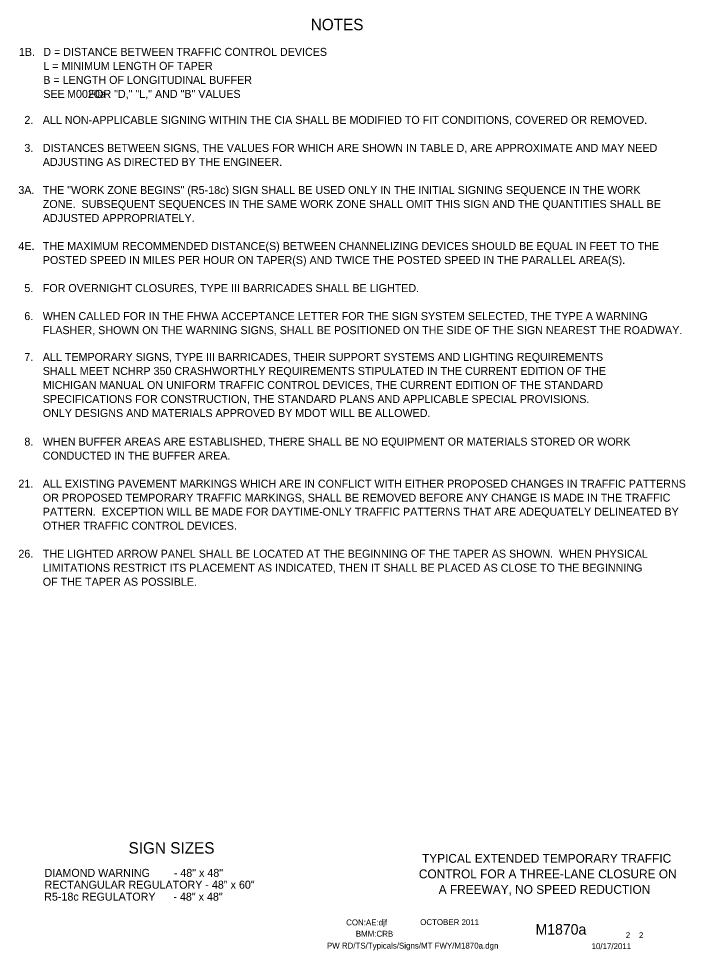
# Model space of a CAD drawing. Extents: x 16724 to 18475, y 7025 to 8210.
# Drawn here: x 17776 to 18475, y 7218 to 8195 of the extents above; entities that cross this region are included whole.
import ezdxf

# ---------------------------------------------------------------- set-up
doc = ezdxf.new("R2010")
doc.units = 0
for name, color, linetype in [('BORDER', 7, 'Continuous'), ('BORDER_SIGNAL_WO', 7, 'Continuous'), ('TYPICAL_TEXT_DIMEN_PR', 7, 'Continuous')]:
    doc.layers.add(name, color=color, linetype=linetype)

msp = doc.modelspace()

# ---------------------------------------------------------------- linework, layer by layer
at = {"layer": 'BORDER'}
msp.add_line((18318.25, 7297.5), (18318.25, 7297.5), dxfattribs=at)

# ---------------------------------------------------------------- texts
for s, p in [('TYPICAL EXTENDED TEMPORARY TRAFFIC', (18199.19, 7309.95)), ('CONTROL FOR A THREE-LANE CLOSURE ON', (18195.91, 7293.65)), ('A FREEWAY, NO SPEED REDUCTION', (18216.69, 7277.35))]:
    msp.add_text(s, height=9.3, dxfattribs=at).set_placement(p)
at = {"layer": 'BORDER_SIGNAL_WO'}
for s, height, p in [('CON:AE:djf  ', 6.2, (18119.69, 7244.31)), ('    OCTOBER 2011', 6.2, (18188.08, 7244.59)), ('    M1870a   ', 11, (18301.86, 7234.63)), ('BMM:CRB', 6.2, (18129.81, 7232.42)), (' 2    2 ', 6.2, (18410.45, 7230.95)), ('PW RD/TS/Typicals/Signs/MT FWY/M1870a.dgn      ', 6.2, (18099.55, 7219.96)), ('10/17/2011', 6.2, (18376.93, 7219.38))]:
    msp.add_text(s, height=height, dxfattribs=at).set_placement(p)
at = {"layer": 'TYPICAL_TEXT_DIMEN_PR'}
for s, height, p in [('NOTES', 12, (18082.55, 8183.25)), ('1B.', 8.4, (17776.71, 8156.36)), ('D = DISTANCE BETWEEN TRAFFIC CONTROL DEVICES', 8.4, (17802.22, 8156.36)), ('L = MINIMUM LENGTH OF TAPER', 8.4, (17802.22, 8141.66)), ('B = LENGTH OF LONGITUDINAL BUFFER', 8.4, (17802.22, 8126.96)), ('SEE        FOR "D," "L," AND "B" VALUES', 8.4, (17802.22, 8112.26)), ('M0020a', 8.4, (17827.14, 8112.26)), ('2.', 8.4, (17782.39, 8085)), ('ALL NON-APPLICABLE SIGNING WITHIN THE CIA SHALL BE MODIFIED TO FIT CONDITIONS, COVERED OR REMOVED.', 8.4, (17801.7, 8085)), ('3.', 8.4, (17782.39, 8055.6)), ('DISTANCES BETWEEN SIGNS, THE VALUES FOR WHICH ARE SHOWN IN TABLE D, ARE APPROXIMATE AND MAY NEED', 8.4, (17801.7, 8055.6)), ('ADJUSTING AS DIRECTED BY THE ENGINEER.', 8.4, (17801.7, 8040.9)), ('3A.', 8.4, (17776.09, 8011.49)), ('THE "WORK ZONE BEGINS" (R5-18c) SIGN SHALL BE USED ONLY IN THE INITIAL SIGNING SEQUENCE IN THE WORK', 8.4, (17801.7, 8011.49)), ('ZONE.  SUBSEQUENT SEQUENCES IN THE SAME WORK ZONE SHALL OMIT THIS SIGN AND THE QUANTITIES SHALL BE', 8.4, (17801.7, 7996.79)), ('ADJUSTED APPROPRIATELY.', 8.4, (17801.7, 7982.09)), ('4E.', 8.4, (17776.13, 7952.7)), ('THE MAXIMUM RECOMMENDED DISTANCE(S) BETWEEN CHANNELIZING DEVICES SHOULD BE EQUAL IN FEET TO THE', 8.4, (17801.7, 7952.7)), ('POSTED SPEED IN MILES PER HOUR ON TAPER(S) AND TWICE THE POSTED SPEED IN THE PARALLEL AREA(S).', 8.4, (17801.7, 7938)), ('5.', 8.4, (17782.39, 7908.6)), ('FOR OVERNIGHT CLOSURES, TYPE III BARRICADES SHALL BE LIGHTED.', 8.4, (17801.7, 7908.6)), ('6.', 8.4, (17782.34, 7879.2)), ('WHEN CALLED FOR IN THE FHWA ACCEPTANCE LETTER FOR THE SIGN SYSTEM SELECTED, THE TYPE A WARNING ', 8.4, (17801.7, 7879.2)), ('FLASHER, SHOWN ON THE WARNING SIGNS, SHALL BE POSITIONED ON THE SIDE OF THE SIGN NEAREST THE ROADWAY.', 8.4, (17801.7, 7864.5)), ('7.', 8.4, (17782.34, 7836.33)), ('ALL TEMPORARY SIGNS, TYPE III BARRICADES, THEIR SUPPORT SYSTEMS AND LIGHTING REQUIREMENTS', 8.4, (17801.7, 7836.35)), ('SHALL MEET NCHRP 350 CRASHWORTHLY REQUIREMENTS STIPULATED IN THE CURRENT EDITION OF THE', 8.4, (17801.7, 7821.65)), ('MICHIGAN MANUAL ON UNIFORM TRAFFIC CONTROL DEVICES, THE CURRENT EDITION OF THE STANDARD', 8.4, (17801.7, 7806.95)), ('SPECIFICATIONS FOR CONSTRUCTION, THE STANDARD PLANS AND APPLICABLE SPECIAL PROVISIONS.', 8.4, (17801.7, 7792.25)), ('ONLY DESIGNS AND MATERIALS APPROVED BY MDOT WILL BE ALLOWED.', 8.4, (17801.7, 7777.55)), ('8.', 8.4, (17782.39, 7747.54)), ('WHEN BUFFER AREAS ARE ESTABLISHED, THERE SHALL BE NO EQUIPMENT OR MATERIALS STORED OR WORK     ', 8.4, (17801.7, 7747.54)), ('CONDUCTED IN THE BUFFER AREA.', 8.4, (17801.7, 7732.84)), ('21.', 8.4, (17776.14, 7703.44)), ('ALL EXISTING PAVEMENT MARKINGS WHICH ARE IN CONFLICT WITH EITHER PROPOSED CHANGES IN TRAFFIC PATTERNS', 8.4, (17801.7, 7703.44)), ('OR PROPOSED TEMPORARY TRAFFIC MARKINGS, SHALL BE REMOVED BEFORE ANY CHANGE IS MADE IN THE TRAFFIC', 8.4, (17801.7, 7688.74)), ('PATTERN.  EXCEPTION WILL BE MADE FOR DAYTIME-ONLY TRAFFIC PATTERNS THAT ARE ADEQUATELY DELINEATED BY', 8.4, (17801.7, 7674.04)), ('OTHER TRAFFIC CONTROL DEVICES.', 8.4, (17801.7, 7659.34)), ('26.', 8.4, (17776.09, 7629.94)), ('THE LIGHTED ARROW PANEL SHALL BE LOCATED AT THE BEGINNING OF THE TAPER AS SHOWN.  WHEN PHYSICAL', 8.4, (17801.7, 7629.94)), ('LIMITATIONS RESTRICT ITS PLACEMENT AS INDICATED, THEN IT SHALL BE PLACED AS CLOSE TO THE BEGINNING', 8.4, (17801.7, 7615.24)), ('OF THE TAPER AS POSSIBLE.', 8.4, (17801.7, 7600.54)), ('SIGN SIZES', 12, (17891.61, 7319.56)), ('DIAMOND WARNING        - 48" x 48"', 8.4, (17803.57, 7295.16)), ('RECTANGULAR REGULATORY - 48" x 60"', 8.4, (17803.57, 7282.76)), ('R5-18c REGULATORY      - 48" x 48"', 8.4, (17803.14, 7270.22))]:
    msp.add_text(s, height=height, dxfattribs=at).set_placement(p)

doc.saveas('drawing.dxf')
